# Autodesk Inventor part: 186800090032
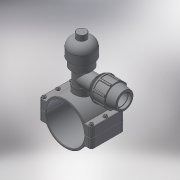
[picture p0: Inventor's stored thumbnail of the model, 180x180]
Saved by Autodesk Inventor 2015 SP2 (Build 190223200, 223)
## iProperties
Created: 2017-05
Part Number: 186800090032
Material: Generic
Description: PLASSON MECHANICAL TAPPING VALVE 90-32
Document SubType Name: Modeling
Designer: KIM
Density: 1 g/cm^3
Appearance: Default
Author: KIM
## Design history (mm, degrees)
derived "18680.ipt"
feature "Solid1::18680.ipt"
feature "Solid2::18680.ipt"
tag "TaggingFeature1"
body "Solid1"
other parameters: "d0" = 99, "d1" = 141, "d2" = 45, "d4" = 105, "d5" = 0, "d6" = 7.05, "d7" = 141, "d8" = 0.1, "d10" = 0, "d11" = 0.9, "d14" = 50.6376, "d20" = 0.9, "d23" = 0.9, "d36" = 13, "d37" = 10.4, "d38" = 53, "d39" = 0, "d40" = 3, "d41" = 5, "d42" = 0, "d43" = 8, "d44" = 3, "d45" = 0, "d46" = 0.9, "d52" = 38.952, "d53" = 25, "d54" = 0, "d55" = 32, "d57" = 0, "d58" = 97.2, "d60" = 0, "d62" = 13, "d63" = 10.4, "d66" = 84.2, "d67" = 32, "d68" = 11.25, "d69" = 27, "d70" = 64, "d71" = 48, "d72" = 1.92857, "d73" = 51.2, "d74" = 120 deg, "d75" = 48, "d76" = 10 deg, "d77" = 57.6, "d78" = 40.5, "d79" = 67, "d80" = 25.6, "d81" = 135, "d82" = 6.7, "d87" = 19.28571, "d90" = 59.52, "d91" = 35 deg, "d92" = 17.5 deg, "d94" = 0, "d96" = 360 deg, "d98" = 0.64, "d99" = 73.7, "d100" = 38.4, "d101" = 135 deg, "d102" = 1.28, "d105" = 3.2, "d106" = 0, "d107" = 0.1, "d109" = 50.6376, "d112" = 34.85714, "d113" = 4.5, "d116" = 0, "d121" = 46.7424, "d122" = 77.904, "d123" = 66.2184, "d124" = 45 deg, "d125" = 219.6, "d126" = 244, "d127" = 146.4, "d128" = 1, "B_" = 32, "G_" = 38.952, "L_" = 141, "L_1" = 105, "l_2" = 25, "d_1" = 32, "E_" = 64, "l_" = 67, "H_" = 135, "H_2" = 244
